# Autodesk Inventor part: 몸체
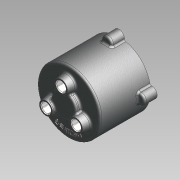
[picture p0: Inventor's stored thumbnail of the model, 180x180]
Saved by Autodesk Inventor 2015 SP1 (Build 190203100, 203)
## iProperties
Company: 한국ATC센터
Created: 2014-07
Part Number: 몸체
Document SubType Name: 모델링
Designer: KYOUNG IL JANG
Material: 알루미늄 6061
Mass: 473.798 g
Surface Area: 687.661 cm^2
Volume: 175.481 cm^3
Density: 2.7 g/cm^3
Appearance: 알루미늄 - 평지
변환 표준: STEP AP214IS
파일 이름: C:\Users\SeoGD\Desktop\?쒗뿕\紐몄껜.stp
전처리기: Build: 253, Release: 2010 SP1 - Date: Wed 07/29/2009
전송 단위: 밀리미터
불확실성: 0.01
Author: KYOUNG IL JANG
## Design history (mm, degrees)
sketch "스케치2"
  geometry: C1 r 50 at (0, 0); 1 further point
  constraints: 1 centre point, 1 coincident
  dimensions: "d9" = 100 diameter of C1
extrude "돌출2" new body sketch "스케치2" distance "d10" = 80; taper "d11" = 0 deg
feature "쉘1" dims "d12" = 5
sketch "스케치3" dims "d13" = 55
  geometry: C1 r 7.5 at (0, 27.5); C2 r 12.5 at (0, 27.5); 2 further points
  constraints: 2 centre point, 2 coincident, 2 vertical alignment, 2 other
  dimensions: "d14" = 15 diameter of C1; "d15" = 25 diameter of C2
extrude "돌출3" join sketch "스케치3" distance "d16" = 12; taper "d17" = -10 deg
hole "구멍2" diameter "d20" = 15; stored, may be unused: countersink angle "d24" = 90 deg, drill point angle "d26" = 118 deg; dims "d18" = 10, "d19" = 10, "d21" = 6, "d22" = 4, "d23" = 2, "d25" = 15
chamfer "모따기1" distance "d27" = 1; stored, may be unused: second distance "d28" = 2, angle "d29" = 45 deg
sketch "스케치4"
  geometry: L1 (0, 0)-(0, 88); L2 (0, 70)-(13.16, 70); L3 (-45, 75)-(45, 75) reference; L4 (-50, 80)-(50, 80) reference; L5 (13.16, 70)-(14.5, 75); L6 (20, 80)-(20, 88); L7 (20, 88)-(0, 88); L8 (20, 80)-(14.5, 75)
  constraints: 12 end point, 3 point on line, 2 perpendicular, 1 vertical
  dimensions: "d34" = 40 diameter of L6 L1; "d35" = 105 deg angle of L5 L3; "d36" = 5 distance between parallel lines of L2 L3; "d37" = 8 distance between parallel lines of L7 L4; "d51" = 29 diameter of L5.end L1
revolve "회전1" sketch "스케치4" stored, may be unused: angle "d38" = 90 deg
hole "구멍3" diameter "d41" = 15; stored, may be unused: countersink angle "d45" = 90 deg, drill point angle "d47" = 0 deg; dims "d39" = 10, "d40" = 10, "d42" = 6, "d43" = 22, "d44" = 13, "d46" = 15
chamfer "모따기2" distance "d48" = 1; stored, may be unused: second distance "d49" = 2, angle "d50" = 45 deg
fillet "모깎기1" dims "d52" = 3
fillet "모깎기2" dims "d53" = 3, "d72" = 0.2
sketch "스케치5"
  geometry: A1 r 50 centre (0, 0) between (50, 0) and (-8.074, 49.344) reference; A2 r 8.5 centre (0, 52) between (8.074, 49.344) and (-8.074, 49.344); 1 further point
  constraints: 5 point on circle, 1 centre point, 1 horizontal alignment
  dimensions: "d54" = 90 deg dimension on point (0, 0) A2.centre A1.start; "d55" = 52 distance of A2.centre point (0, 0); "d56" = 17 diameter of A2
extrude "돌출4" join sketch "스케치5" distance "d57" = 20; taper "d58" = 0 deg
fillet "모깎기3" dims "d59" = 3
hole "구멍4" diameter "d62" = 4.134; stored, may be unused: countersink angle "d66" = 90 deg, drill point angle "d68" = 118 deg; dims "d60" = 10, "d61" = 10, "d63" = 12, "d64" = 22, "d65" = 13, "d67" = 15
sketch "스케치6"
  geometry: C1 r 47 at (0, 0) reference; C2 r 42.5 at (0, 0); 1 further point
  constraints: 1 centre point, 1 coincident, 1 other
  dimensions: "d73" = 85 diameter of C2
feature "엠보싱1" sketch "스케치6" dims "d74" = 1, "d75" = 0
node "솔리드1"
node "솔리드 본체"
node "곡면 본체"
pattern_circular "원형 패턴1" dims "d31" = 360 deg
pattern_circular "원형 패턴2" dims "d70" = 360 deg
node "솔리드2"
